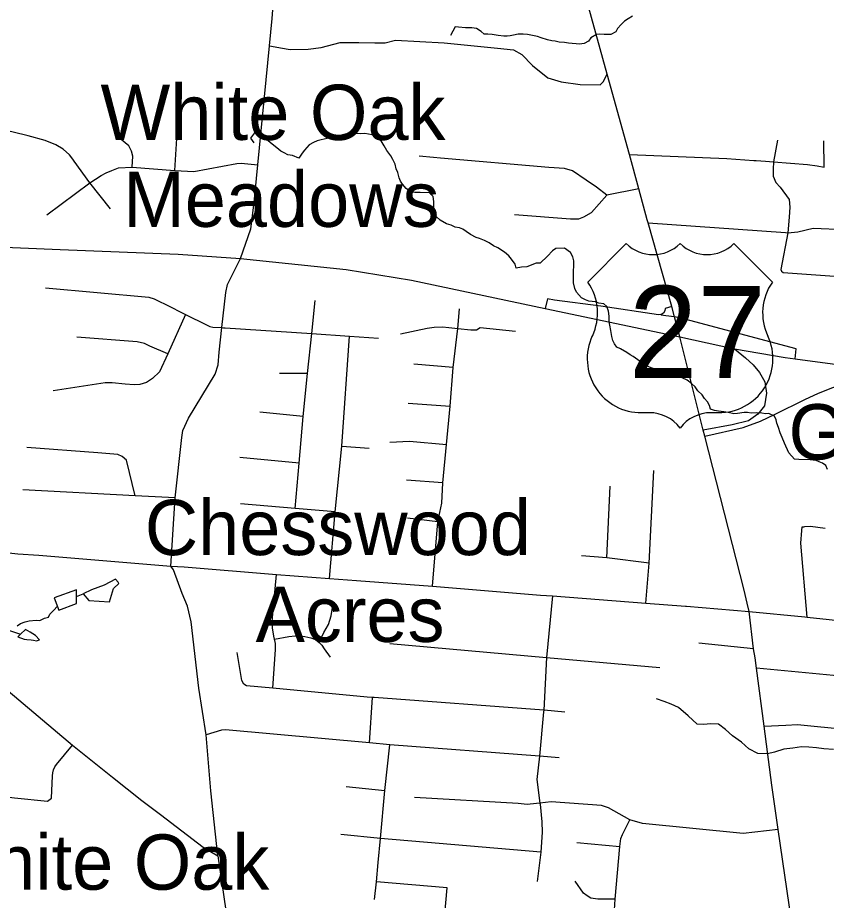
# Model space of a CAD drawing. Extents: x 0 to 34, y 0 to 22.
# Drawn here: x 3.408 to 4.564, y 15.023 to 16.285 of the extents above; entities that cross this region are included whole.
import ezdxf

# ---------------------------------------------------------------- set-up
doc = ezdxf.new("R2010")
doc.units = 0
for name, color, linetype in [('GM_X_County_Road', 7, 'Continuous'), ('GM_X_Interchange_Ramps', 7, 'Continuous'), ('GM_X_Minor_Lake', 7, 'Continuous'), ('GM_X_Minor_River', 7, 'Continuous'), ('GM_X_State_Route', 7, 'Continuous'), ('GM_X_Township_Subdivision', 7, 'Continuous'), ('GM_X_Unincorporated_Text', 7, 'Continuous'), ('GM_X_US_Location', 7, 'Continuous'), ('GM_X_US_Route', 7, 'Continuous'), ('GM_X_US_Shield', 7, 'Continuous')]:
    doc.layers.add(name, color=color, linetype=linetype)

msp = doc.modelspace()

# ---------------------------------------------------------------- linework, layer by layer
at = {"layer": 'GM_X_County_Road'}
for points in [[(3.6274, 15.5008), (3.6334, 15.5983), (3.6428, 15.6844), (3.6442, 15.6947), (3.6526, 15.7123), (3.6907, 15.7752), (3.6948, 15.7884), (3.6964, 15.8066), (3.7002, 15.8416), (3.7057, 15.8918), (3.7083, 15.9035), (3.7269, 15.9403), (3.7414, 15.9828), (3.7462, 16.0207), (3.7514, 16.0744), (3.7681, 16.2443), (3.7721, 16.2837), (3.7888, 16.4987)], [(3.7681, 16.2443), (3.7764, 16.243), (3.7839, 16.2415), (3.798, 16.2394), (3.8233, 16.2398), (3.8421, 16.2421), (3.8692, 16.2492), (3.8959, 16.2492), (3.9188, 16.2485), (3.9335, 16.2489), (3.9482, 16.2526), (4.0178, 16.2489), (4.0942, 16.2413), (4.1168, 16.2387), (4.1288, 16.2319), (4.1443, 16.2165), (4.1661, 16.1988), (4.1849, 16.1928), (4.2124, 16.1894), (4.2406, 16.1887), (4.2449, 16.193), (4.2509, 16.204)], [(2.0624, 16.1544), (2.0789, 16.1495), (2.3218, 16.0727), (2.3948, 16.0576), (2.5679, 16.0322), (2.6419, 16.0249), (2.8264, 16.0064), (2.913, 15.9963), (3.15, 15.9729), (3.2871, 15.9607), (3.469, 15.9531), (3.6377, 15.9467), (3.7269, 15.9403), (3.8777, 15.9247), (3.9714, 15.9095), (4.1621, 15.8689), (4.3548, 15.8285)], [(4.3548, 15.8285), (4.4326, 15.8115)], [(4.4326, 15.8115), (4.4486, 15.7985), (4.4596, 15.7885), (4.4686, 15.7775), (4.4761, 15.764), (4.4786, 15.748), (4.4756, 15.73), (4.4661, 15.718), (4.4526, 15.7085), (4.4296, 15.7025), (4.3881, 15.6951)], [(3.1437, 15.5578), (3.2132, 15.5475), (3.3147, 15.5315), (3.3657, 15.5231), (3.4084, 15.5185), (3.4388, 15.5162), (3.6274, 15.5008)], [(3.6945, 15.0867), (3.6842, 15.1793), (3.6775, 15.2598), (3.6674, 15.3264), (3.6565, 15.421), (3.6512, 15.4435), (3.6436, 15.4618), (3.631, 15.4952), (3.6274, 15.5008)], [(3.6274, 15.5008), (3.6461, 15.4998), (3.7781, 15.4889), (3.8541, 15.483), (3.8925, 15.4802), (4.001, 15.472), (4.1557, 15.4593), (4.1727, 15.4582), (4.306, 15.4477), (4.3627, 15.4437), (4.3641, 15.4436)], [(4.3641, 15.4436), (4.4536, 15.436)], [(4.4536, 15.436), (4.5333, 15.4281)], [(4.5333, 15.4281), (4.5365, 15.4278), (4.6218, 15.4186), (4.7103, 15.4103), (4.7637, 15.4056), (4.8525, 15.397), (4.9822, 15.3853), (5.1507, 15.3687)], [(3.3884, 15.3276), (3.4866, 15.245), (3.5439, 15.199), (3.5857, 15.1656), (3.6126, 15.1455), (3.6735, 15.0988), (3.6945, 15.0867)], [(3.6945, 15.0867), (3.7086, 14.9889), (3.7089, 14.9865), (3.7134, 14.9601), (3.7288, 14.8681), (3.7325, 14.8589)]]:
    msp.add_lwpolyline(points, dxfattribs=at)
at = {"layer": 'GM_X_Interchange_Ramps'}
for points in [[(4.343, 15.8718), (4.3335, 15.8691), (4.3334, 15.8655), (4.3313, 15.8624), (4.3291, 15.8608), (4.3276, 15.8605), (4.3243, 15.8601), (4.2417, 15.8721), (4.1754, 15.881), (4.1654, 15.8826), (4.1621, 15.8689)], [(4.347, 15.8571), (4.3347, 15.8584), (4.3278, 15.8595), (4.3276, 15.8605)], [(4.5196, 15.797), (4.5211, 15.8115), (4.3546, 15.8557), (4.347, 15.8571)]]:
    msp.add_lwpolyline(points, dxfattribs=at)
at = {"layer": 'GM_X_Minor_Lake'}
for points in [[(3.502, 15.461), (3.5098, 15.4518), (3.5394, 15.4496), (3.5451, 15.4689), (3.5529, 15.4759), (3.5518, 15.4779), (3.5481, 15.4821), (3.5319, 15.4737), (3.5139, 15.4669)], [(3.4673, 15.438), (3.4922, 15.4473), (3.4926, 15.4666), (3.4605, 15.4552)], [(3.5139, 15.4669), (3.502, 15.461)], [(3.4605, 15.4552), (3.4673, 15.438)], [(3.4122, 15.4033), (3.4087, 15.3998), (3.4174, 15.3961), (3.4216, 15.396), (3.4276, 15.3955), (3.431, 15.3951), (3.4352, 15.3938), (3.4394, 15.3953), (3.4338, 15.4015), (3.4263, 15.4062), (3.4197, 15.4099)], [(3.4197, 15.4099), (3.4122, 15.4033)]]:
    msp.add_lwpolyline(points, dxfattribs=at)
at = {"layer": 'GM_X_Minor_River'}
for points in [[(4.2868, 16.2868), (4.281, 16.2831), (4.2756, 16.2799), (4.2709, 16.275), (4.2658, 16.2691), (4.2634, 16.2646), (4.2561, 16.2606), (4.2515, 16.2604), (4.2466, 16.2605), (4.2405, 16.261), (4.2355, 16.2604), (4.2274, 16.2557), (4.2243, 16.2512), (4.2181, 16.2476), (4.2112, 16.247), (4.2067, 16.2471), (4.201, 16.2477), (4.1957, 16.2482), (4.1896, 16.2491), (4.1824, 16.2497), (4.1767, 16.251), (4.1718, 16.2515), (4.1657, 16.2529), (4.1563, 16.2558), (4.1514, 16.2578)], [(4.1514, 16.2578), (4.1439, 16.2592), (4.137, 16.2605), (4.1306, 16.2611), (4.1234, 16.2613), (4.1169, 16.2599), (4.1123, 16.2589), (4.1077, 16.2583), (4.1031, 16.2584), (4.0952, 16.259), (4.0865, 16.2604), (4.0804, 16.2609), (4.0751, 16.2611), (4.0706, 16.265), (4.0643, 16.269), (4.0574, 16.2703), (4.0483, 16.2702), (4.0381, 16.2713), (4.0335, 16.2718), (4.0271, 16.259)], [(4.1657, 15.944), (4.1552, 15.934), (4.1495, 15.9338), (4.136, 15.9285), (4.1284, 15.9279), (4.1208, 15.9266), (4.1194, 15.9324), (4.1143, 15.9397), (4.1102, 15.9444), (4.1039, 15.9495), (4.0945, 15.9555), (4.0885, 15.9587), (4.0822, 15.9627), (4.0754, 15.9663), (4.0683, 15.9688), (4.0634, 15.9705), (4.0555, 15.9749), (4.0495, 15.9792), (4.0443, 15.9824), (4.0398, 15.9845), (4.0334, 15.9854), (4.0277, 15.9882), (4.0213, 15.9899), (4.0123, 15.9951), (4.0064, 16.0003), (4.0031, 16.0064), (4.0029, 16.0133), (4.0032, 16.0221), (4.0019, 16.0293), (3.9967, 16.0344), (3.9837, 16.0348), (3.9758, 16.0346), (3.9705, 16.0355), (3.9637, 16.0403), (3.9582, 16.0465), (3.9553, 16.0512), (3.9535, 16.0558), (3.9518, 16.0635), (3.9493, 16.0685), (3.9476, 16.0754), (3.9447, 16.0819), (3.9414, 16.087), (3.9359, 16.0948), (3.9323, 16.1017), (3.9279, 16.1087), (3.9224, 16.1146), (3.9149, 16.1174), (3.9043, 16.1193), (3.8982, 16.1187), (3.8902, 16.1193), (3.8784, 16.1188), (3.8635, 16.1147), (3.8547, 16.113), (3.842, 16.1103), (3.8363, 16.1086), (3.8309, 16.1061), (3.8251, 16.1028), (3.8184, 16.0954), (3.8149, 16.0909), (3.8101, 16.0838), (3.8011, 16.0875), (3.7943, 16.0888), (3.7894, 16.0916), (3.7842, 16.094), (3.7786, 16.0988), (3.7719, 16.1039), (3.7663, 16.1086), (3.7586, 16.1169), (3.7522, 16.1201), (3.7469, 16.1202), (3.7413, 16.1124), (3.7457, 16.1058)], [(4.5659, 15.6389), (4.5634, 15.6446), (4.5585, 15.6478), (4.554, 15.6499), (4.5495, 15.6515), (4.5408, 15.6525), (4.5248, 15.653), (4.5184, 15.6535), (4.5102, 15.6629), (4.5041, 15.6764), (4.5009, 15.6848), (4.4981, 15.6914), (4.4956, 15.6987), (4.4935, 15.7052), (4.4925, 15.7098), (4.49, 15.7149), (4.4817, 15.7189), (4.4771, 15.7186), (4.4718, 15.7196), (4.4642, 15.7198), (4.4566, 15.7196), (4.4513, 15.7201), (4.4464, 15.7203), (4.4372, 15.719), (4.4319, 15.7184), (4.4239, 15.7201), (4.4175, 15.7214), (4.4099, 15.7224), (4.4043, 15.7233), (4.3986, 15.725), (4.3972, 15.7304), (4.3943, 15.7358), (4.3899, 15.7405), (4.3866, 15.7455), (4.3803, 15.7514), (4.3766, 15.7569), (4.3715, 15.762), (4.3651, 15.7667), (4.358, 15.7699), (4.3392, 15.7773), (4.3301, 15.7795), (4.3165, 15.7833), (4.3112, 15.785), (4.306, 15.7874), (4.3007, 15.7906), (4.2948, 15.7957), (4.2881, 15.8005), (4.2836, 15.8029), (4.2791, 15.806), (4.2697, 15.8113), (4.2645, 15.8137), (4.2612, 15.8187), (4.2587, 15.8234), (4.2573, 15.8291), (4.256, 15.8375), (4.2547, 15.8452), (4.2537, 15.8498), (4.2535, 15.8582), (4.2526, 15.8654), (4.2505, 15.8716), (4.246, 15.8755), (4.2388, 15.8765), (4.2339, 15.8785), (4.2244, 15.8795), (4.2199, 15.8816), (4.2143, 15.8844), (4.2069, 15.8922), (4.2048, 15.8976), (4.2027, 15.9057), (4.2029, 15.911), (4.2026, 15.9156), (4.2028, 15.922), (4.2034, 15.9304), (4.2032, 15.9369), (4.2018, 15.9426), (4.1982, 15.9492), (4.19, 15.9551), (4.1774, 15.9547), (4.1728, 15.9514), (4.1657, 15.944)], [(3.4924, 15.4574), (3.502, 15.461)], [(3.4075, 15.4153), (3.4126, 15.4186), (3.4191, 15.4211), (3.4248, 15.4224), (3.4348, 15.4233), (3.4401, 15.4232), (3.4466, 15.4264), (3.4524, 15.4278), (3.4543, 15.4322), (3.4594, 15.4372), (3.4651, 15.4435)], [(3.3865, 15.4148), (3.3953, 15.4094), (3.4122, 15.4033)], [(4.5741, 15.2384), (4.5604, 15.2395), (4.5502, 15.2409), (4.5388, 15.242), (4.5286, 15.2426), (4.516, 15.2406), (4.5034, 15.239), (4.49, 15.2348), (4.4801, 15.2324), (4.466, 15.2331), (4.4532, 15.2395), (4.4428, 15.2489), (4.4301, 15.2583), (4.4201, 15.2673), (4.41, 15.2748), (4.3986, 15.2754), (4.3891, 15.2741), (4.3792, 15.2747), (4.3666, 15.2865), (4.3528, 15.2986), (4.3423, 15.3034), (4.3321, 15.3071), (4.3212, 15.3111)]]:
    msp.add_lwpolyline(points, dxfattribs=at)
at = {"layer": 'GM_X_State_Route'}
for points in [[(4.4326, 15.8115), (4.5051, 15.799), (4.5196, 15.797), (4.6332, 15.782)], [(4.3903, 15.6863), (4.4453, 15.699), (4.4698, 15.7077), (4.4911, 15.7177), (4.5331, 15.7387), (4.5528, 15.7478), (4.5732, 15.7562), (4.5922, 15.7616), (4.6126, 15.7705), (4.6332, 15.782)]]:
    msp.add_lwpolyline(points, dxfattribs=at)
at = {"layer": 'GM_X_Township_Subdivision'}
for points in [[(3.4871, 16.0822), (3.4822, 16.0885), (3.4734, 16.0966), (3.4629, 16.1028), (3.4476, 16.1091), (3.4233, 16.1159), (3.4019, 16.1209), (3.362, 16.1302), (3.3606, 16.1298)], [(3.5718, 16.0708), (3.5727, 16.0867), (3.5708, 16.0938), (3.5671, 16.1013), (3.5487, 16.1168)], [(3.6331, 16.0664), (3.6359, 16.1119)], [(4.4605, 16.0806), (4.4639, 16.0803), (4.4773, 16.0796), (4.4885, 16.0787), (4.537, 16.0747), (4.5509, 16.0731), (4.5607, 16.0708), (4.5604, 16.1085)], [(4.4944, 16.1096), (4.4885, 16.0787), (4.4881, 16.0683), (4.488, 16.0579), (4.492, 16.0491), (4.498, 16.0426), (4.5111, 16.0246), (4.5119, 16.014), (4.5111, 15.9993), (4.5088, 15.9773), (4.4992, 15.9245), (4.4999, 15.9222), (4.5025, 15.9206), (4.669, 15.9083), (4.7263, 15.9033)], [(4.2826, 16.089), (4.4218, 16.0834), (4.4605, 16.0806)], [(3.4498, 16.0027), (3.5117, 16.0487), (3.5276, 16.059), (3.5347, 16.0627), (3.543, 16.0662), (3.5522, 16.0699), (3.5718, 16.0708), (3.6331, 16.0664), (3.6601, 16.0646), (3.7217, 16.0764), (3.7277, 16.0769), (3.7514, 16.0744)], [(3.541, 16.0114), (3.5117, 16.0487), (3.489, 16.0798), (3.4871, 16.0822)], [(4.0025, 16.0848), (3.9822, 16.0866)], [(4.2961, 16.0399), (4.2505, 16.0312), (4.2355, 16.0424), (4.2208, 16.0524), (4.2011, 16.0656), (4.1896, 16.0689), (4.1676, 16.0707), (4.0126, 16.0839), (4.0025, 16.0848)], [(4.1185, 16.0034), (4.1982, 15.997), (4.2105, 15.9971), (4.2175, 16.0001), (4.2284, 16.0064), (4.2505, 16.0312)], [(4.3094, 15.9915), (4.5055, 15.9776)], [(4.5055, 15.9776), (4.5088, 15.9773), (4.5235, 15.9786), (4.545, 15.9838), (4.5904, 15.982), (4.6449, 15.9751), (4.6518, 15.9745)], [(3.448, 15.8985), (3.5959, 15.885), (3.6034, 15.8826), (3.6102, 15.8793), (3.6199, 15.8746), (3.6481, 15.8604), (3.678, 15.8454), (3.6829, 15.8434), (3.6874, 15.8425), (3.7002, 15.8416), (3.7025, 15.8415), (3.7048, 15.8413)], [(3.8047, 15.5833), (3.8107, 15.6481), (3.8165, 15.7144), (3.8224, 15.7763), (3.8285, 15.8331), (3.8336, 15.8806)], [(3.6481, 15.8604), (3.6231, 15.8043), (3.6108, 15.7783), (3.6011, 15.7689), (3.5923, 15.7634), (3.5831, 15.7604), (3.5747, 15.7598), (3.5621, 15.761), (3.5436, 15.7629), (3.5332, 15.7628), (3.459, 15.7513)], [(4.001, 15.472), (4.0089, 15.5639), (4.0147, 15.5907), (4.0159, 15.62), (4.0213, 15.6745), (4.0266, 15.7292), (4.0305, 15.7846), (4.0373, 15.8404), (4.0397, 15.8686)], [(3.7048, 15.8413), (3.8285, 15.8331), (3.8824, 15.8295), (3.9238, 15.8267)], [(3.9555, 15.8328), (3.9935, 15.8407), (4.0037, 15.8424), (4.0156, 15.8428), (4.0244, 15.8417), (4.0373, 15.8404), (4.0562, 15.8385), (4.0639, 15.8383), (4.0695, 15.8416), (4.1198, 15.8367)], [(3.6231, 15.8043), (3.5973, 15.8153), (3.5895, 15.8191), (3.5792, 15.8213), (3.493, 15.8281)], [(3.8541, 15.483), (3.8621, 15.5782), (3.8718, 15.672), (3.8824, 15.8295)], [(4.0305, 15.7846), (3.9744, 15.7894)], [(3.8224, 15.7763), (3.7825, 15.7763)], [(3.9662, 15.7337), (4.0266, 15.7292)], [(3.8165, 15.7144), (3.7542, 15.7208)], [(3.8718, 15.672), (3.9107, 15.6694)], [(3.9401, 15.6778), (3.9683, 15.6793), (4.0213, 15.6745)], [(3.5764, 15.6013), (3.564, 15.6521), (3.5579, 15.6576), (3.5517, 15.6602), (3.5231, 15.6629), (3.4216, 15.6702)], [(3.8107, 15.6481), (3.726, 15.6562)], [(4.306, 15.4477), (4.3107, 15.5051), (4.3175, 15.6376)], [(4.0159, 15.62), (3.9639, 15.6238)], [(3.6334, 15.5983), (3.5764, 15.6013), (3.4156, 15.6096)], [(4.2504, 15.5127), (4.255, 15.6149)], [(3.8621, 15.5782), (3.8047, 15.5833), (3.7268, 15.5897)], [(4.0089, 15.5639), (3.9654, 15.5691)], [(4.5321, 15.5571), (4.5335, 15.5572), (4.5412, 15.5577), (4.5624, 15.5552)], [(4.5365, 15.4278), (4.5278, 15.5333), (4.5288, 15.5516), (4.5293, 15.5568), (4.5321, 15.5571)], [(4.3107, 15.5051), (4.2504, 15.5127), (4.2141, 15.5153)], [(3.7732, 15.3262), (3.7768, 15.3814), (3.7766, 15.3901), (3.7754, 15.3964), (3.7746, 15.4004), (3.7726, 15.4123), (3.772, 15.421), (3.7729, 15.4327), (3.7781, 15.4889)], [(4.1727, 15.4582), (4.1643, 15.37), (4.1602, 15.2947), (4.16, 15.2925)], [(3.8393, 15.3915), (3.8461, 15.4059), (3.8524, 15.4175), (3.8565, 15.4299), (3.8592, 15.4473)], [(3.7754, 15.3964), (3.7959, 15.4003), (3.8049, 15.401), (3.8059, 15.401)], [(3.8059, 15.401), (3.8094, 15.401), (3.8186, 15.4003), (3.8273, 15.3984), (3.8341, 15.3956), (3.8393, 15.3915), (3.8429, 15.3875), (3.8464, 15.3826), (3.855, 15.3707)], [(3.9401, 15.3899), (4.1643, 15.37), (4.3263, 15.3556)], [(4.4601, 15.3824), (4.382, 15.3906)], [(3.908, 15.3136), (3.7732, 15.3262), (3.7352, 15.3296), (3.7315, 15.332), (3.7286, 15.337), (3.722, 15.3771)], [(4.6365, 15.3382), (4.6244, 15.3396), (4.4644, 15.355)], [(3.9177, 15.3128), (3.9155, 15.3129), (3.908, 15.3136)], [(3.911, 15.248), (3.9155, 15.3129)], [(4.1609, 15.2947), (4.1602, 15.2947), (3.9177, 15.3128)], [(4.16, 15.2925), (4.1543, 15.2289), (4.1505, 15.1956), (4.1547, 15.162), (4.1549, 15.1603)], [(4.1901, 15.2921), (4.1609, 15.2947)], [(4.4752, 15.2718), (4.5061, 15.2736), (4.523, 15.2745), (4.5946, 15.2672)], [(4.182, 15.2266), (4.1543, 15.2289), (3.9403, 15.2453), (3.911, 15.248), (3.7052, 15.2666), (3.6995, 15.2663), (3.6775, 15.2598)], [(3.3433, 15.1746), (3.3838, 15.1717), (3.4039, 15.1695), (3.4508, 15.1648), (3.4566, 15.1692), (3.4581, 15.201), (3.4585, 15.2052), (3.4596, 15.2095), (3.4615, 15.2137), (3.4636, 15.2171), (3.4866, 15.245)], [(3.9237, 15.0772), (3.9271, 15.1113), (3.9331, 15.18), (3.9403, 15.2453)], [(3.878, 15.1859), (3.9331, 15.18)], [(4.1407, 15.1605), (4.1367, 15.16), (4.1236, 15.1612), (3.9756, 15.1702)], [(4.4954, 15.1244), (4.4454, 15.1183), (4.3015, 15.1329), (4.2831, 15.1383), (4.2528, 15.1554), (4.2429, 15.1584), (4.1706, 15.1636), (4.1547, 15.162), (4.1407, 15.1605)], [(4.1549, 15.1603), (4.1575, 15.135), (4.158, 15.1205), (4.1558, 15.0917), (4.1508, 15.0501)], [(4.1976, 14.8897), (4.2019, 14.9169), (4.2042, 14.9255), (4.2086, 14.9327), (4.254, 14.9884), (4.2586, 14.9962), (4.2613, 15.0095), (4.2622, 15.0246), (4.2689, 15.1001), (4.2701, 15.1112), (4.2729, 15.1172), (4.2831, 15.1383)], [(4.1558, 15.0917), (3.9271, 15.1113), (3.8703, 15.117)], [(4.2073, 15.1056), (4.2689, 15.1001)], [(3.9185, 15.0241), (3.921, 15.0495), (3.9237, 15.0772)], [(4.0106, 14.9118), (4.0222, 15.0411), (3.921, 15.0495)], [(4.2622, 15.0246), (4.2377, 15.0246), (4.2276, 15.0263), (4.222, 15.0296), (4.2171, 15.0334), (4.2053, 15.0503)]]:
    msp.add_lwpolyline(points, dxfattribs=at)
at = {"layer": 'GM_X_US_Route'}
for points in [[(4.347, 15.8571), (4.343, 15.8718), (4.3094, 15.9915), (4.3082, 15.9958), (4.2961, 16.0399), (4.2826, 16.089), (4.2509, 16.204), (4.2124, 16.3441), (4.1884, 16.4342), (4.1794, 16.4679), (4.1431, 16.6089), (4.0889, 16.8066), (4.0359, 17.0028), (4.0043, 17.1198), (3.9604, 17.2824), (3.9324, 17.3858)], [(4.3548, 15.8285), (4.347, 15.8571)], [(4.3903, 15.6863), (4.3881, 15.6951), (4.3548, 15.8285)], [(4.4494, 15.4539), (4.4464, 15.4662), (4.3903, 15.6863)], [(4.5242, 14.9225), (4.5208, 14.9494), (4.5159, 14.9833), (4.5144, 14.9937), (4.4954, 15.1244), (4.4862, 15.1877), (4.4752, 15.2718), (4.4644, 15.355), (4.4625, 15.3694), (4.4601, 15.3824), (4.4536, 15.436), (4.4509, 15.4477), (4.4494, 15.4539)]]:
    msp.add_lwpolyline(points, dxfattribs=at)
at = {"layer": 'GM_X_US_Shield'}
for p, q in [((4.2781, 15.9618), (4.2232, 15.9068)), ((4.4869, 15.9068), (4.4319, 15.9618)), ((4.3001, 15.7201), (4.3111, 15.7201)), ((4.399, 15.7201), (4.41, 15.7201))]:
    msp.add_line(p, q, dxfattribs=at)
for centre, radius, start, end in [((4.3166, 16.001), 0.0549, 225.573, 314.427), ((4.3935, 16.001), 0.0549, 225.573, 314.427), ((4.1602, 15.8627), 0.0769, 334.5471, 35.0009), ((4.5499, 15.8627), 0.0769, 144.9991, 205.4529), ((4.2992, 15.797), 0.0769, 154.8319, 270.6383), ((4.4108, 15.797), 0.0769, 269.3617, 25.1681), ((4.3111, 15.6651), 0.0549, 36.8699, 90), ((4.399, 15.6651), 0.0549, 90, 143.1301)]:
    msp.add_arc(centre, radius, start, end, dxfattribs=at)

# ---------------------------------------------------------------- texts
at = {"layer": 'GM_X_Unincorporated_Text'}
for s, p in [('White Oak', (3.5267, 16.1099)), ('Meadows', (3.5592, 15.9857)), ('Groesbeck', (4.51, 15.6532)), ('Chesswood', (3.59, 15.5165)), ('Acres', (3.7484, 15.3924)), ('White Oak', (3.275, 15.0382))]:
    msp.add_text(s, height=0.07898, rotation=0, dxfattribs=at).set_placement(p)
at = {"layer": 'GM_X_US_Location'}
for s in ['0', '/']:
    msp.add_text(s, height=0.000189, dxfattribs=at).set_placement((4.355, 15.8344))
msp.add_text('27', height=0.000189, rotation=0, dxfattribs=at).set_placement((4.3159, 15.7952))
at = {"layer": 'GM_X_US_Shield'}
msp.add_text('27', height=0.13184, dxfattribs=at).set_placement((4.2817, 15.7695))

doc.saveas('drawing.dxf')
